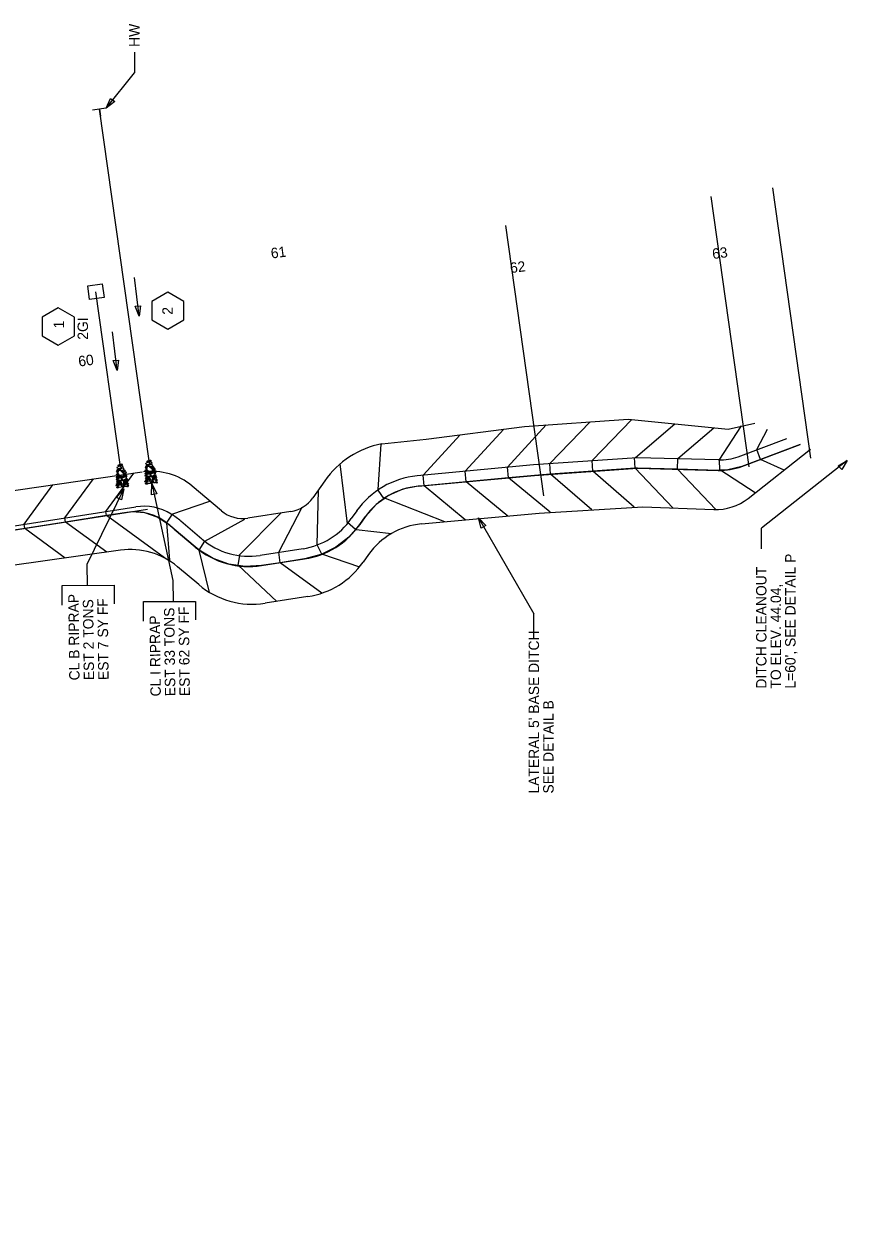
# Model space of a CAD drawing. Extents: x 2384780 to 2405432, y 547869 to 573706.
# Drawn here: x 2394260 to 2394656, y 553776 to 554350 of the extents above; entities that cross this region are included whole.
import ezdxf

# ---------------------------------------------------------------- set-up
doc = ezdxf.new("R2010")
doc.units = 0
for name, color, linetype in [('Old_Level_1', 7, 'Continuous'), ('Old_Level_18', 7, 'Continuous'), ('Old_Level_23', 7, 'Continuous'), ('Old_Level_5', 7, 'Continuous'), ('Old_Level_63', 7, 'Continuous'), ('Old_Level_9', 7, 'Continuous'), ('Prop Ditch Text', 7, 'Continuous'), ('Prop Drainage Box Number Symbol CELL', 7, 'Continuous'), ('Prop Lateral Base Ditch Detail CELL', 7, 'Continuous')]:
    doc.layers.add(name, color=color, linetype=linetype)

# ---------------------------------------------------------------- blocks, each defined once
blk = doc.blocks.new('IN')
at = {"layer": 'Old_Level_9'}
blk.add_lwpolyline([(-0.07025, 0.067), (0.07025, 0.067), (0.07025, -0.067), (-0.07025, -0.067)], close=True, dxfattribs=at)
blk = doc.blocks.new('RIPRAP')
at = {"layer": 'Old_Level_1'}
for points in [[(-0.002, -0.00625), (-0.00625, -0.00775), (-0.016, -0.0125), (-0.02, -0.00675), (-0.02, -0.003), (-0.008, 0.00275), (-0.002, -0.00025), (-0.002, -0.00625)], [(0.01825, -0.00325), (0.01375, -0.005), (0.00325, -0.00975), (0.00025, -0.00375), (0, 0), (0.01125, 0.005), (0.018, 0.00275), (0.01825, -0.00325)], [(-0.046, -0.12775), (-0.0505, -0.12425), (-0.053, -0.1145), (-0.0485, -0.11), (-0.04475, -0.11), (-0.04, -0.12175), (-0.04225, -0.12625), (-0.046, -0.12775)], [(-0.0485, -0.08525), (-0.0425, -0.0835), (-0.03275, -0.0825), (-0.0305, -0.08925), (-0.03175, -0.0945), (-0.0445, -0.09325), (-0.049, -0.089), (-0.0485, -0.08525)], [(-0.046, -0.1025), (-0.04025, -0.098), (-0.02675, -0.09375), (-0.02, -0.09975), (-0.02, -0.10575), (-0.03625, -0.11225), (-0.044, -0.1085), (-0.046, -0.1025)], [(-0.03675, -0.07275), (-0.04075, -0.06825), (-0.04325, -0.0585), (-0.0395, -0.054), (-0.035, -0.054), (-0.031, -0.0665), (-0.033, -0.0705), (-0.03675, -0.07275)], [(-0.023, -0.1195), (-0.02725, -0.12175), (-0.037, -0.126), (-0.041, -0.1195), (-0.041, -0.11625), (-0.029, -0.1115), (-0.02525, -0.1135), (-0.023, -0.1195)], [(-0.0305, -0.05975), (-0.035, -0.05625), (-0.0375, -0.0465), (-0.033, -0.042), (-0.02925, -0.042), (-0.02475, -0.05375), (-0.02675, -0.05825), (-0.0305, -0.05975)], [(-0.00025, -0.11525), (-0.0145, -0.10575), (-0.0355, -0.078), (-0.0255, -0.056), (-0.00975, -0.051), (0.01725, -0.08475), (0.01525, -0.10425), (0.002, -0.11775)], [(-0.0345, -0.0215), (-0.0265, -0.01775), (-0.007, -0.01125), (0.00375, -0.02075), (0.003, -0.0315), (-0.02075, -0.03775), (-0.03225, -0.032), (-0.0345, -0.024)], [(-0.0275, -0.0395), (-0.023, -0.03925), (-0.014, -0.039), (-0.0115, -0.045), (-0.0115, -0.04875), (-0.0235, -0.049), (-0.0295, -0.04475), (-0.0275, -0.0395)], [(-0.01575, -0.1245), (-0.02025, -0.12125), (-0.022, -0.11125), (-0.0185, -0.10675), (-0.014, -0.10675), (-0.00975, -0.1185), (-0.012, -0.123), (-0.01575, -0.1245)], [(-0.0095, -0.039), (0.00025, -0.0365), (0.0205, -0.036), (0.02775, -0.0495), (0.024, -0.05775), (-0.00075, -0.05675), (-0.009, -0.0485), (-0.0095, -0.039)], [(0.009, -0.07425), (0.0045, -0.07075), (0.00225, -0.061), (0.00625, -0.05625), (0.01, -0.057), (0.01425, -0.06825), (0.01275, -0.072), (0.009, -0.07425)], [(0.012, -0.0355), (0.00825, -0.0295), (0.0035, -0.01775), (0.01025, -0.00925), (0.01825, -0.009), (0.0225, -0.027), (0.01875, -0.033), (0.012, -0.0355)], [(0.01975, -0.07925), (0.01525, -0.07475), (0.01375, -0.06525), (0.01725, -0.0605), (0.02175, -0.0605), (0.02575, -0.07325), (0.0235, -0.077), (0.01975, -0.07925)], [(0.0225, -0.12), (0.0185, -0.11625), (0.01675, -0.10675), (0.0205, -0.102), (0.025, -0.102), (0.0285, -0.114), (0.02625, -0.11775), (0.0225, -0.12)], [(0.02025, -0.07975), (0.02825, -0.07725), (0.04025, -0.077), (0.045, -0.08725), (0.042, -0.0935), (0.02475, -0.092), (0.02025, -0.0855), (0.02025, -0.07975)], [(0.03125, -0.0765), (0.0265, -0.073), (0.02425, -0.06325), (0.0285, -0.0585), (0.03225, -0.05925), (0.03625, -0.0705), (0.035, -0.07425), (0.03125, -0.0765)], [(0.048, -0.1195), (0.04425, -0.12325), (0.036, -0.12575), (0.03, -0.122), (0.02975, -0.1155), (0.04175, -0.11375), (0.04775, -0.11575), (0.048, -0.1195)], [(0.03775, -0.114), (0.03325, -0.11025), (0.031, -0.1005), (0.035, -0.096), (0.03875, -0.09675), (0.043, -0.10775), (0.0415, -0.1115), (0.03775, -0.114)], [(-0.06725, -0.1915), (-0.06125, -0.18975), (-0.0515, -0.18875), (-0.04925, -0.1955), (-0.0505, -0.20075), (-0.06325, -0.1995), (-0.06775, -0.19525), (-0.06725, -0.1915)], [(-0.064, -0.2115), (-0.058, -0.20975), (-0.04825, -0.20875), (-0.046, -0.2155), (-0.04725, -0.22075), (-0.06, -0.2195), (-0.0645, -0.21525), (-0.064, -0.2115)], [(-0.061, -0.17925), (-0.055, -0.17725), (-0.04525, -0.17625), (-0.043, -0.183), (-0.04425, -0.18825), (-0.057, -0.187), (-0.0615, -0.18275), (-0.061, -0.17925)], [(-0.04975, -0.14825), (-0.05425, -0.14475), (-0.05675, -0.135), (-0.05225, -0.1305), (-0.0485, -0.1305), (-0.04375, -0.14225), (-0.046, -0.14675), (-0.04975, -0.14825)], [(-0.04975, -0.17575), (-0.05375, -0.1705), (-0.05675, -0.16075), (-0.05225, -0.157), (-0.04875, -0.157), (-0.04375, -0.169), (-0.046, -0.1735), (-0.04975, -0.17575)], [(-0.032, -0.15425), (-0.03625, -0.15575), (-0.046, -0.158), (-0.0505, -0.15375), (-0.05075, -0.15075), (-0.041, -0.146), (-0.035, -0.14825), (-0.03275, -0.152)], [(-0.05075, -0.19675), (-0.0405, -0.195), (-0.021, -0.194), (-0.01375, -0.208), (-0.018, -0.21775), (-0.042, -0.21675), (-0.0505, -0.20725), (-0.05075, -0.19675)], [(-0.04275, -0.12825), (-0.03225, -0.126), (-0.012, -0.1275), (-0.00575, -0.1395), (-0.009, -0.15), (-0.033, -0.1485), (-0.04375, -0.13875), (-0.04275, -0.12825)], [(-0.0355, -0.17625), (-0.037, -0.1725), (-0.04125, -0.16275), (-0.03525, -0.158), (-0.0315, -0.158), (-0.02675, -0.17075), (-0.031, -0.174), (-0.0355, -0.17625)], [(-0.012, -0.187), (-0.01875, -0.19075), (-0.033, -0.1935), (-0.039, -0.1875), (-0.039, -0.1815), (-0.02275, -0.17675), (-0.01525, -0.17875), (-0.012, -0.187)], [(-0.0215, -0.16975), (-0.02625, -0.1655), (-0.0285, -0.15575), (-0.024, -0.15125), (-0.02025, -0.15175), (-0.01625, -0.163), (-0.01775, -0.1675), (-0.0215, -0.16975)], [(0.00075, -0.15075), (0.0045, -0.15875), (0.011, -0.179), (0.0015, -0.18875), (-0.009, -0.189), (-0.01475, -0.16525), (-0.012, -0.153), (-0.0015, -0.1515)], [(-0.0115, -0.204), (-0.00425, -0.2025), (0.0085, -0.20225), (0.01275, -0.21275), (0.01125, -0.2185), (-0.0075, -0.21675), (-0.01225, -0.21075), (-0.0115, -0.204)], [(-0.00575, -0.118), (0.00025, -0.1155), (0.0085, -0.1175), (0.0125, -0.12425), (0.01025, -0.128), (-0.00175, -0.12825), (-0.00575, -0.12175), (-0.00575, -0.118)], [(0.04, -0.14075), (0.03075, -0.14625), (0.009, -0.15575), (-0.004, -0.14175), (-0.00425, -0.132), (0.024, -0.123), (0.03825, -0.1285), (0.0425, -0.1405)], [(0.00625, -0.2035), (0.00175, -0.19975), (-0.001, -0.19), (0.0035, -0.1855), (0.00725, -0.1855), (0.012, -0.1975), (0.01, -0.202), (0.00625, -0.2035)], [(0.01625, -0.174), (0.0125, -0.17075), (0.009, -0.16), (0.0135, -0.1555), (0.01725, -0.15625), (0.022, -0.168), (0.02075, -0.17175), (0.01625, -0.174)], [(0.026, -0.18075), (0.03225, -0.18875), (0.03875, -0.20825), (0.02925, -0.219), (0.01875, -0.21675), (0.012, -0.193), (0.01575, -0.184), (0.026, -0.17925)], [(0.0205, -0.15575), (0.0265, -0.15325), (0.03475, -0.15525), (0.03875, -0.162), (0.0365, -0.16575), (0.0245, -0.166), (0.0205, -0.1595), (0.0205, -0.15575)], [(0.04925, -0.17425), (0.044, -0.17875), (0.03525, -0.1805), (0.02975, -0.177), (0.0295, -0.171), (0.0415, -0.16925), (0.0475, -0.1705), (0.04925, -0.17425)], [(0.0335, -0.189), (0.0395, -0.18675), (0.04775, -0.18875), (0.0515, -0.1955), (0.04925, -0.19925), (0.03725, -0.1995), (0.0335, -0.19275), (0.0335, -0.189)], [(0.043, -0.162), (0.03825, -0.1585), (0.036, -0.14875), (0.04, -0.144), (0.04375, -0.14475), (0.048, -0.15575), (0.04675, -0.1595), (0.043, -0.162)], [(0.04325, -0.22375), (0.0385, -0.22025), (0.03625, -0.2105), (0.0405, -0.20575), (0.04425, -0.2065), (0.0485, -0.2175), (0.047, -0.22125), (0.04325, -0.22375)]]:
    blk.add_lwpolyline(points, dxfattribs=at)
blk = doc.blocks.new('HDWL')
at = {"layer": 'Old_Level_1'}
for p, q in [((0, 0), (-0.0685, 0)), ((0, -0.0655), (0, 0.0685))]:
    blk.add_line(p, q, dxfattribs=at)
blk = doc.blocks.new('AH1')
at = {"layer": 'Old_Level_23'}
blk.add_lwpolyline([(-5.28, 1.32), (0, 0), (-5.28, -1.32)], close=True, dxfattribs=at)

msp = doc.modelspace()

# ---------------------------------------------------------------- linework, layer by layer
at = {"layer": 'Old_Level_1'}
for p, q in [((2394319.96, 554140.06), (2394296.08, 554309.46)), ((2394306.09, 554138.18), (2394294.35, 554221.45)), ((2394478.67, 554112.54), (2394505.41, 554066.27))]:
    msp.add_line(p, q, dxfattribs=at)
for points in [[(2394321.31, 554129.03), (2394331.49, 554082.29), (2394331.53, 554072.23)], [(2394307.8, 554126.48), (2394290.06, 554090.02), (2394290.1, 554079.97)], [(2394278.14, 554070.48), (2394278.1, 554079.92), (2394303.18, 554080.02), (2394303.22, 554071.18)], [(2394317.28, 554062.74), (2394317.24, 554072.18), (2394342.32, 554072.28), (2394342.36, 554063.43)]]:
    msp.add_lwpolyline(points, dxfattribs=at)
msp.add_lwpolyline([(2394480.09, 554107.58), (2394478.67, 554112.54), (2394482.26, 554108.83)], close=True, dxfattribs=at)
at = {"layer": 'Old_Level_18'}
for points in [[(2394432.15, 554148.21), (2394453.55, 554150.42), (2394500.95, 554156.55), (2394550.83, 554160.07), (2394599, 554155.19), (2394611.91, 554158.18)], [(2394354.81, 554115.97), (2394340.76, 554127.84)], [(2394404.61, 554130.3), (2394398.93, 554122.22)], [(2394388.3, 554115.6), (2394367.59, 554112.38)], [(2394420.02, 554115.84), (2394417.43, 554112.15)], [(2394345.48, 554102.31), (2394335.29, 554110.93)], [(2394394.16, 554097.67), (2394373.46, 554094.45)], [(2394425.75, 554094.84), (2394423.16, 554091.15)], [(2394343.89, 554080.36), (2394333.69, 554088.98)], [(2394396.56, 554074.6), (2394375.86, 554071.38)]]:
    msp.add_lwpolyline(points, dxfattribs=at)
for centre, radius, start, end in [((2394440.62, 554105.03), 44, 101.10556, 144.94759), ((2394321.39, 554104.93), 30, 49.78981, 97.73613), ((2394385.84, 554131.41), 16, 278.84284, 324.94743), ((2394365.13, 554128.19), 16, 229.79045, 278.84268), ((2394388.78, 554132.25), 35, 278.84284, 324.94743), ((2394368.08, 554129.03), 35, 229.79045, 278.84268), ((2394390.41, 554114.13), 40, 278.84284, 324.94743), ((2394369.71, 554110.91), 40, 229.79045, 278.84268)]:
    msp.add_arc(centre, radius, start, end, dxfattribs=at)
at = {"layer": 'Old_Level_5'}
for p, q in [((2394312.88, 554336.88), (2394312.88, 554326.88)), ((2394299.32, 554309.92), (2394312.88, 554326.88)), ((2394315.19, 554209.62), (2394312.94, 554228.27)), ((2394304.54, 554183.45), (2394302.29, 554202.1)), ((2394599, 554155.19), (2394611.91, 554158.18)), ((2394505.41, 554056.27), (2394505.41, 554066.27))]:
    msp.add_line(p, q, dxfattribs=at)
for points in [[(2394303.42, 554313.05), (2394299.32, 554309.92), (2394301.46, 554314.61)], [(2394315.83, 554214.73), (2394315.19, 554209.62), (2394313.35, 554214.43)], [(2394305.19, 554188.56), (2394304.54, 554183.45), (2394302.7, 554188.26)]]:
    msp.add_lwpolyline(points, close=True, dxfattribs=at)
at = {"layer": 'Old_Level_63'}
for p, q in [((2394638.92, 554141.29), (2394620.56, 554271.49)), ((2394609.21, 554137.1), (2394590.85, 554267.3)), ((2394510.19, 554123.14), (2394491.83, 554253.34))]:
    msp.add_line(p, q, dxfattribs=at)
at = {"layer": 'Prop Ditch Text'}
for p in [(2394656.39, 554140.22), (2394615.1, 554097.6)]:
    msp.add_line(p, (2394615.1, 554107.6), dxfattribs=at)
msp.add_lwpolyline([(2394651.99, 554137.54), (2394656.39, 554140.22), (2394653.77, 554135.78)], close=True, dxfattribs=at)
at = {"layer": 'Prop Drainage Box Number Symbol CELL'}
for points in [[(2394329, 554221.27), (2394321.25, 554216.79), (2394321.25, 554207.84), (2394329, 554203.37), (2394336.75, 554207.84), (2394336.75, 554216.79)], [(2394276.22, 554213.63), (2394268.47, 554209.16), (2394268.47, 554200.21), (2394276.22, 554195.73), (2394283.97, 554200.21), (2394283.97, 554209.16)]]:
    msp.add_lwpolyline(points, close=True, dxfattribs=at)
at = {"layer": 'Prop Lateral Base Ditch Detail CELL'}
for p, q in [((2394492.67, 554136.91), (2394511.42, 554157.29)), ((2394513.14, 554138.65), (2394532.56, 554158.78)), ((2394533.52, 554140.08), (2394552.63, 554159.89)), ((2394554.39, 554141.63), (2394573.37, 554157.79)), ((2394574.81, 554141.06), (2394592.22, 554155.88)), ((2394594.79, 554140.36), (2394605.53, 554156.79)), ((2394451.99, 554133.08), (2394469.89, 554152.53)), ((2394472.33, 554134.99), (2394490.98, 554155.26)), ((2394603.93, 554141.99), (2394627.34, 554150.78)), ((2394612.9, 554145.48), (2394618, 554155.31)), ((2394430.32, 554126.21), (2394431.79, 554147.96)), ((2394605.69, 554137.31), (2394633.82, 554147.87)), ((2394608.64, 554121.87), (2394638.79, 554145.54)), ((2394614.69, 554140.69), (2394612.9, 554145.48)), ((2394415.55, 554109.65), (2394412.03, 554138.48)), ((2394513.5, 554133.55), (2394513.14, 554138.65)), ((2394533.87, 554134.99), (2394533.52, 554140.08)), ((2394554.25, 554136.42), (2394553.89, 554141.52)), ((2394574.67, 554135.96), (2394574.81, 554141.06)), ((2394595.09, 554135.45), (2394594.83, 554140.55)), ((2394626.05, 554135.54), (2394614.69, 554140.69)), ((2394235.4, 554122.87), (2394316.68, 554134.66)), ((2394452.47, 554127.99), (2394451.99, 554133.08)), ((2394472.81, 554129.91), (2394472.33, 554134.99)), ((2394493.14, 554131.82), (2394492.67, 554136.91)), ((2394533.32, 554116.34), (2394513.5, 554133.55)), ((2394553.83, 554117.65), (2394533.87, 554134.99)), ((2394572.39, 554117.34), (2394554.25, 554136.53)), ((2394593.05, 554116.53), (2394574.67, 554135.96)), ((2394612.06, 554124.56), (2394595.04, 554135.61)), ((2394472.38, 554111.51), (2394452.47, 554127.99)), ((2394492.81, 554113.35), (2394472.81, 554129.91)), ((2394513.23, 554115.19), (2394493.14, 554131.82)), ((2394400.93, 554099.56), (2394401.61, 554125.8)), ((2394433.31, 554121.75), (2394430.33, 554125.89)), ((2394462.57, 554110.62), (2394433.04, 554122.23)), ((2394330.87, 554114.32), (2394349.2, 554120.54)), ((2394382.43, 554095.95), (2394393.7, 554117.73)), ((2394328.44, 554110.01), (2394331.22, 554114.29)), ((2394330.02, 554092.08), (2394328.51, 554110.1)), ((2394346.82, 554101.35), (2394366.09, 554111.92)), ((2394363.36, 554094.48), (2394383.4, 554114.84)), ((2394419.48, 554106.91), (2394415.61, 554110.25)), ((2394436.83, 554104.8), (2394419.73, 554106.72)), ((2394344.17, 554096.99), (2394346.82, 554101.35)), ((2394403.19, 554094.98), (2394400.93, 554099.56)), ((2394349.15, 554076.6), (2394344.17, 554096.99)), ((2394362.95, 554089.56), (2394363.69, 554094.61)), ((2394383.22, 554090.91), (2394382.43, 554095.95)), ((2394421.5, 554088.79), (2394403.19, 554094.98)), ((2394381.47, 554072.25), (2394362.89, 554089.76)), ((2394403.28, 554076.25), (2394383.22, 554090.91))]:
    msp.add_line(p, q, dxfattribs=at)
for points in [[(2394633.82, 554147.87), (2394614.69, 554140.69), (2394605.69, 554137.31), (2394598.97, 554135.64), (2394595.09, 554135.45), (2394594.31, 554135.41), (2394574.67, 554135.96), (2394555.32, 554136.5), (2394554.25, 554136.42), (2394533.87, 554134.99), (2394513.5, 554133.55), (2394505.7, 554133), (2394493.14, 554131.82), (2394472.81, 554129.91), (2394452.47, 554127.99), (2394449.64, 554127.73), (2394449.62, 554127.73), (2394442.29, 554126.27), (2394435.44, 554123.28), (2394433.31, 554121.75), (2394429.38, 554118.91), (2394424.39, 554113.35), (2394424.11, 554112.97), (2394421.52, 554109.28), (2394419.48, 554106.91), (2394416.31, 554103.23), (2394409.99, 554098.34), (2394403.19, 554094.98), (2394402.82, 554094.8), (2394395.1, 554092.76), (2394394.93, 554092.73), (2394383.22, 554090.91), (2394374.23, 554089.51), (2394366.25, 554089.08), (2394362.95, 554089.56), (2394358.34, 554090.24), (2394350.83, 554092.95), (2394344.17, 554096.99), (2394344, 554097.09), (2394342.26, 554098.49), (2394332.06, 554107.11), (2394329.23, 554109.5), (2394328.44, 554110.01), (2394323.93, 554112.93), (2394317.94, 554114.93), (2394311.65, 554115.37), (2394309.23, 554115.11)], [(2394594.45, 554140.41), (2394555.22, 554141.5), (2394505.29, 554137.99), (2394449.17, 554132.71)], [(2394327.36, 554093.24), (2394299.49, 554113.59), (2394299.49, 554113.59), (2394299.49, 554113.59), (2394299.18, 554115.58), (2394312.7, 554134.08)], [(2394449.64, 554127.73), (2394505.7, 554133), (2394555.32, 554136.5), (2394594.31, 554135.41)], [(2394279.6, 554093.15), (2394260.03, 554107.44), (2394260.03, 554107.44), (2394260.03, 554107.44), (2394259.72, 554109.42), (2394273.59, 554128.41)], [(2394299.66, 554095.98), (2394279.76, 554110.51), (2394279.76, 554110.51), (2394279.76, 554110.51), (2394279.45, 554112.5), (2394293.14, 554131.25)], [(2393196.22, 553777.45), (2393241.79, 553798.07), (2393284.03, 553819.54), (2393328.78, 553841.92), (2393371.76, 553862.08), (2393417.78, 553881.63), (2393462.19, 553898.46), (2393508.68, 553916.88), (2393553.28, 553933.12), (2393600.43, 553949.75), (2393645.79, 553963.79), (2393693.59, 553978.52), (2393739.13, 553991.69), (2393787.29, 554005.17), (2393833.16, 554016.98), (2393881.59, 554029.44), (2393927.62, 554040.32), (2393976.18, 554052.24), (2394022.24, 554062.95), (2394071.05, 554073.79), (2394117.3, 554083.73), (2394166.25, 554093.93), (2394212.88, 554102.11), (2394313.55, 554117.81)], [(2393197.09, 553775.66), (2393242.67, 553796.28), (2393284.86, 553817.72), (2393329.61, 553840.1), (2393372.54, 553860.24), (2393418.56, 553879.79), (2393462.93, 553896.6), (2393509.41, 553915.02), (2393553.96, 553931.24), (2393601.12, 553947.87), (2393646.43, 553961.89), (2393694.22, 553976.62), (2393739.71, 553989.78), (2393787.88, 554003.25), (2393833.69, 554015.05), (2393882.12, 554027.51), (2393928.11, 554038.38), (2393976.67, 554050.29), (2394022.68, 554061), (2394071.49, 554071.84), (2394117.68, 554081.77), (2394166.64, 554091.97), (2394213.21, 554100.13), (2394319.22, 554116.67)], [(2394451.26, 554109.6), (2394507.96, 554114.71), (2394557.92, 554117.91), (2394592.22, 554116.56)], [(2394309.23, 554115.11), (2394299.49, 554113.59), (2394279.76, 554110.51), (2394260.03, 554107.44), (2394240.3, 554104.36), (2394230.76, 554102.87)], [(2394421.52, 554109.28), (2394424.11, 554112.97)], [(2394332.06, 554107.11), (2394342.26, 554098.49)], [(2394306.2, 554096.91), (2394234.52, 554086.78)], [(2394374.23, 554089.51), (2394394.93, 554092.73)]]:
    msp.add_lwpolyline(points, dxfattribs=at)
for centre, radius, start, end in [((2394595.14, 554165.4), 25, 268.40365, 290.5763), ((2394452.76, 554092.87), 40, 95.15276, 144.94726), ((2394595.14, 554165.4), 30, 268.40365, 290.5763), ((2394452.76, 554092.87), 35, 95.15276, 144.94726), ((2394593.21, 554141.54), 25, 267.7377, 308.12746), ((2394313.09, 554090.41), 25, 49.79006, 98.865), ((2394317.4, 554093.11), 25, 58.04401, 98.86495), ((2394309.46, 554080.38), 40, 49.79006, 58.04401), ((2394314.06, 554088.69), 25.75, 45.66309, 53.91703), ((2394388.78, 554132.25), 40, 278.84284, 324.94743), ((2394454.4, 554074.74), 35, 95.15276, 144.94726), ((2394368.08, 554129.03), 40, 229.79045, 278.84268), ((2394311.1, 554062.25), 35, 49.79006, 98.0402)]:
    msp.add_arc(centre, radius, start, end, dxfattribs=at)

# ---------------------------------------------------------------- block references
at = {"layer": 'Old_Level_1'}
for p, xscale, yscale, rotation in [((2394307.8, 554126.48), 1.0000005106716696, 1.00000051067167, 64.04670709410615), ((2394321.31, 554129.03), 0.9999995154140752, 0.9999995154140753, 102.27929444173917)]:
    msp.add_blockref('AH1', p, dxfattribs=dict(at, xscale=xscale, yscale=yscale, rotation=rotation))
at = {"layer": 'Old_Level_5', "yscale": 50}
for name, p, xscale, rotation in [('HDWL', (2394296.08, 554309.46), 49.99999999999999, 98.02674452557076), ('IN', (2394294.35, 554221.45), 50.00000000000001, 8.012337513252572), ('RIPRAP', (2394306.09, 554138.18), 50.00000000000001, 8.012337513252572), ('RIPRAP', (2394319.96, 554140.06), 49.99999999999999, 8.026744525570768)]:
    msp.add_blockref(name, p, dxfattribs=dict(at, xscale=xscale, rotation=rotation))

# ---------------------------------------------------------------- texts
at = {"layer": 'Old_Level_1'}
for s, p in [('CL B RIPRAP', (2394286.5, 554034.27)), ('EST 2 TONS ', (2394293.5, 554034.36)), ('EST 7 SY FF', (2394300.5, 554034.44)), ('EST 62 SY FF', (2394339.65, 554026.7)), ('CL I RIPRAP', (2394325.65, 554026.53)), ('EST 33 TONS ', (2394332.65, 554026.61))]:
    msp.add_text(s, height=5, rotation=90.68875, dxfattribs=at).set_placement(p)
at = {"layer": 'Old_Level_5'}
for s, p in [('HW', (2394315.38, 554339.38)), ('2GI', (2394290.53, 554198.34)), ("LATERAL 5' BASE DITCH", (2394507.91, 553979.72)), ('SEE DETAIL B', (2394514.91, 553979.72))]:
    msp.add_text(s, height=5, rotation=90, dxfattribs=at).set_placement(p)
at = {"layer": 'Old_Level_63'}
for s, p in [('61', (2394378.97, 554237.44)), ('63', (2394591.68, 554237.17)), ('62', (2394494.24, 554230.41)), ('60', (2394286.19, 554185.39))]:
    msp.add_text(s, height=5, rotation=7.27684, dxfattribs=at).set_placement(p)
at = {"layer": 'Prop Ditch Text'}
for s, p in [("L=60', SEE DETAIL P", (2394631.51, 554030.26)), ('DITCH CLEANOUT', (2394617.51, 554030.26)), ('TO ELEV. 44.04, ', (2394624.51, 554030.26))]:
    msp.add_text(s, height=5, rotation=90, dxfattribs=at).set_placement(p)
at = {"layer": 'Prop Drainage Box Number Symbol CELL'}
for s, p in [('2', (2394331.36, 554210.37)), ('1', (2394279.02, 554203.77))]:
    msp.add_text(s, height=5, rotation=90, dxfattribs=at).set_placement(p)

doc.saveas('drawing.dxf')
